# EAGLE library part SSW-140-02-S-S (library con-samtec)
THROUGH-HOLE .025" SQ POST SOCKET Source: Samtec SSW.pdf
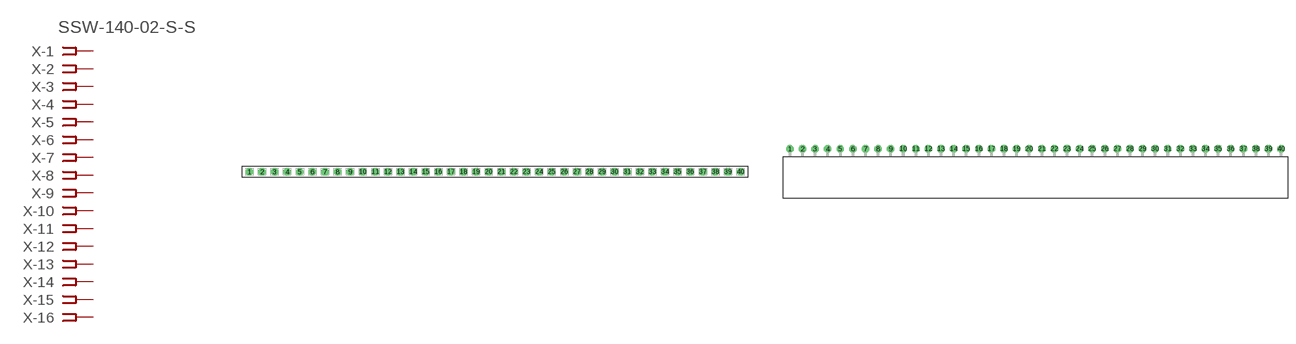
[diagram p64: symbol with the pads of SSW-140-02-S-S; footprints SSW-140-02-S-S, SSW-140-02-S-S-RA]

Designator prefix X; gates -1=FPINV -2=FPIN -3=FPIN -4=FPIN -5=FPIN -6=FPIN -7=FPIN -8=FPIN -9=FPIN -10=FPIN -11=FPIN -12=FPIN -13=FPIN -14=FPIN -15=FPIN -16=FPIN -17=FPIN -18=FPIN -19=FPIN -20=FPIN -21=FPIN -22=FPIN -23=FPIN -24=FPIN -25=FPIN -26=FPIN -27=FPIN -28=FPIN -29=FPIN -30=FPIN -31=FPIN -32=FPIN -33=FPIN -34=FPIN -35=FPIN -36=FPIN -37=FPIN -38=FPIN -39=FPIN -40=FPIN

## SSW-140-02-S-S (MPN: SSW-140-02-S-S; OC_FARNELL: unknown; OC_NEWARK: 11P9957)  [SSW-140-02-S-S]
1  -1:1  pas
2  -2:1  pas
3  -3:1  pas
4  -4:1  pas
5  -5:1  pas
6  -6:1  pas
7  -7:1  pas
8  -8:1  pas
9  -9:1  pas
10  -10:1  pas
11  -11:1  pas
12  -12:1  pas
13  -13:1  pas
14  -14:1  pas
15  -15:1  pas
16  -16:1  pas
17  -17:1  pas
18  -18:1  pas
19  -19:1  pas
20  -20:1  pas
21  -21:1  pas
22  -22:1  pas
23  -23:1  pas
24  -24:1  pas
25  -25:1  pas
26  -26:1  pas
27  -27:1  pas
28  -28:1  pas
29  -29:1  pas
30  -30:1  pas
31  -31:1  pas
32  -32:1  pas
33  -33:1  pas
34  -34:1  pas
35  -35:1  pas
36  -36:1  pas
37  -37:1  pas
38  -38:1  pas
39  -39:1  pas
40  -40:1  pas

## SSW-140-02-S-S-RA (MPN: SSW-140-02-S-S-RA; OC_FARNELL: unknown; OC_NEWARK: 83P1367)  [SSW-140-02-S-S-RA]
Pads as for SSW-140-02-S-S

## Footprint SSW-140-02-S-S (pad centres in mm)
THROUGH-HOLE .025" SQ POST SOCKET Source: Samtec SSW.pdf
drill 1 pad 1.5 octagon: 1 -49.53,0; 2 -46.99,0; 3 -44.45,0; 4 -41.91,0; 5 -39.37,0; 6 -36.83,0; 7 -34.29,0; 8 -31.75,0; 9 -29.21,0; 10 -26.67,0; 11 -24.13,0; 12 -21.59,0; 13 -19.05,0; 14 -16.51,0; 15 -13.97,0; 16 -11.43,0; 17 -8.89,0; 18 -6.35,0; 19 -3.81,0; 20 -1.27,0; 21 1.27,0; 22 3.81,0; 23 6.35,0; 24 8.89,0; 25 11.43,0; 26 13.97,0; 27 16.51,0; 28 19.05,0; 29 21.59,0; 30 24.13,0; 31 26.67,0; 32 29.21,0; 33 31.75,0; 34 34.29,0; 35 36.83,0; 36 39.37,0; 37 41.91,0; 38 44.45,0; 39 46.99,0; 40 49.53,0

## Footprint SSW-140-02-S-S-RA (pad centres in mm)
THROUGH-HOLE .025" SQ POST SOCKET Source: Samtec SSW.pdf
drill 1 pad 1.5 octagon: 1 -49.53,1.524; 2 -46.99,1.524; 3 -44.45,1.524; 4 -41.91,1.524; 5 -39.37,1.524; 6 -36.83,1.524; 7 -34.29,1.524; 8 -31.75,1.524; 9 -29.21,1.524; 10 -26.67,1.524; 11 -24.13,1.524; 12 -21.59,1.524; 13 -19.05,1.524; 14 -16.51,1.524; 15 -13.97,1.524; 16 -11.43,1.524; 17 -8.89,1.524; 18 -6.35,1.524; 19 -3.81,1.524; 20 -1.27,1.524; 21 1.27,1.524; 22 3.81,1.524; 23 6.35,1.524; 24 8.89,1.524; 25 11.43,1.524; 26 13.97,1.524; 27 16.51,1.524; 28 19.05,1.524; 29 21.59,1.524; 30 24.13,1.524; 31 26.67,1.524; 32 29.21,1.524; 33 31.75,1.524; 34 34.29,1.524; 35 36.83,1.524; 36 39.37,1.524; 37 41.91,1.524; 38 44.45,1.524; 39 46.99,1.524; 40 49.53,1.524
